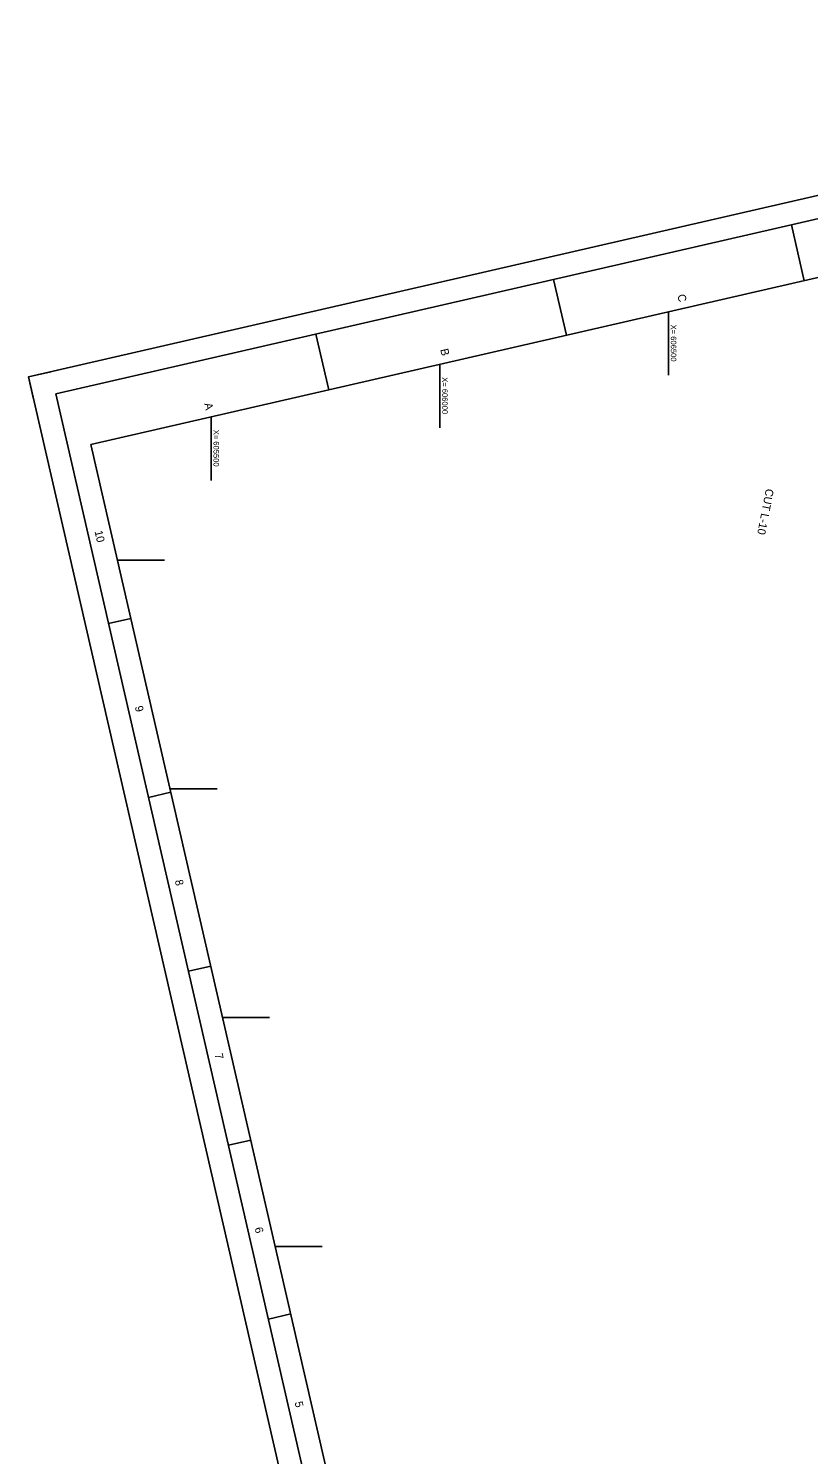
# Model space of a CAD drawing. Extents: x 604101 to 608400, y 789112 to 794162.
# Drawn here: x 604101 to 605806, y 791045 to 794162 of the extents above; entities that cross this region are included whole.
import ezdxf

# ---------------------------------------------------------------- set-up
doc = ezdxf.new("R2010")
doc.units = 0
for name, color, linetype in [('G-ANNO-NPLT', 7, 'Continuous'), ('G-ANNO-TTLB', 7, 'Continuous'), ('V-CHAN-CNTR-IDEN', 7, 'Continuous'), ('V-TOPO-COOR-STAT', 7, 'Continuous')]:
    doc.layers.add(name, color=color, linetype=linetype)

msp = doc.modelspace()

# ---------------------------------------------------------------- linework, layer by layer
at = {"layer": 'G-ANNO-NPLT'}
msp.add_lwpolyline([(607414.4, 794162.2), (608399.7, 789874), (605086.1, 789112.6), (604100.8, 793400.8)], close=True, dxfattribs=at)
msp.add_lwpolyline([(604149.5, 793412), (604100.8, 793400.8), (604112, 793352.1)], dxfattribs=at)
at = {"layer": 'G-ANNO-TTLB'}
for p, q in [((605768.7, 793732.8), (605796.7, 793610.9)), ((605249, 793613.3), (605276.9, 793491.5)), ((604729.2, 793493.9), (604757.2, 793372.1)), ((604276, 792861.4), (604324.8, 792872.6)), ((604363.4, 792481.3), (604412.1, 792492.5)), ((604450.7, 792101.2), (604499.4, 792112.4)), ((604538, 791721.1), (604586.8, 791732.3)), ((604625.4, 791341), (604674.1, 791352.2))]:
    msp.add_line(p, q, dxfattribs=at)
for points in [[(604160.7, 793363.3), (605123.6, 789172.5), (608339.8, 789911.5), (607376.9, 794102.3)], [(608279.9, 789949), (607356.2, 793969.2), (604237.4, 793252.7), (605161.2, 789232.4)]]:
    msp.add_lwpolyline(points, close=True, dxfattribs=at)
at = {"layer": 'V-TOPO-COOR-STAT'}
for p, q in [((605500, 793404.2), (605500, 793542.8)), ((605000, 793289.4), (605000, 793427.9)), ((604500, 793174.5), (604500, 793313)), ((604295.5, 793000), (604398.1, 793000)), ((604410.4, 792500), (604513, 792500)), ((604525.3, 792000), (604627.9, 792000)), ((604640.1, 791500), (604742.8, 791500))]:
    msp.add_line(p, q, dxfattribs=at)

# ---------------------------------------------------------------- texts
at = {"layer": 'G-ANNO-TTLB'}
for s, p in [('C', (605519.4, 793579.3)), ('B', (605001, 793460.4)), ('A', (604484.9, 793342)), ('10', (604245.1, 793062.9)), ('9', (604333.2, 792679.5)), ('8', (604420.5, 792299.5)), ('7', (604507.7, 791920)), ('6', (604595.1, 791539.9)), ('5', (604682.6, 791159))]:
    msp.add_text(s, height=17.5, rotation=282.9401, dxfattribs=at).set_placement(p)
at = {"layer": 'V-CHAN-CNTR-IDEN'}
msp.add_text('CUT L-10', height=17.52, rotation=258.9941, dxfattribs=at).set_placement((605713.4, 793157.2))
at = {"layer": 'V-TOPO-COOR-STAT'}
for s, p in [('X= 606500', (605505.2, 793514.8)), ('X= 606000', (605005.2, 793399.9)), ('X= 605500', (604505.2, 793285.1))]:
    msp.add_text(s, height=12, rotation=270, dxfattribs=at).set_placement(p)

doc.saveas('drawing.dxf')
